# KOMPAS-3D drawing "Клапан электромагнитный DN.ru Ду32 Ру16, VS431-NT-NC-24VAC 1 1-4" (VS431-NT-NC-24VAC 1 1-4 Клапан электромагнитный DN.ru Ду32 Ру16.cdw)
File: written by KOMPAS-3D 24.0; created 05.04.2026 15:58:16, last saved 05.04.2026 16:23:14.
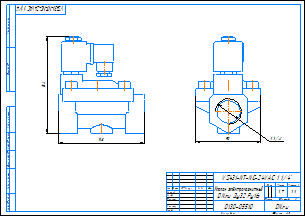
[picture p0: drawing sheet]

Document properties: c3d_UniqueCompID: ef56311e-7521-43dc-8291-0e6108b3d81d; Автор: artio; Класс точности: c; Знак неуказанной шероховатости: Шероховатость не задана; Рассекать на разрезах: Да; c3d_UniqueCompID: ef56311e-7521-43dc-8291-0e6108b3d81d; Автор: artio; Класс точности: c; Знак неуказанной шероховатости: Шероховатость не задана; Рассекать на разрезах: Да; c3d_UniqueCompID: ef56311e-7521-43dc-8291-0e6108b3d81d; Автор: artio; Класс точности: c; Знак неуказанной шероховатости: Шероховатость не задана; Рассекать на разрезах: Да; Автор: artio; Форматы листов документа: A3; Полное имя файла: VS431-NT-NC-24VAC 1 1-4 Клапан электромагнитный DN.ru Ду32 Ру16.m3d; Масса: 1.701; Наименование: Клапан электромагнитный DN.ru Ду32 Ру16; Количество листов документа: 1; Примечание: D130-05510

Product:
- Body: Тело 1  | qty 1
    Масса: 3.709873
- Part/product: Клапан электромагнитный DN.ru Ду32 Ру16  | designation VS431-NT-NC-24VAC 1 1-4
    Масса: 1.701
    Раздел спецификации: Прочие изделия
    Примечание: D130-05510
    additional columns: ef56311e-7521-43dc-8291-0e6108b3d81d; artio; c; Шероховатость не задана; Да

Views: Вид 1, Спереди
Referenced files in C:\Users\artio\OneDrive\Рабочий стол\Клапан электромагнитный DN.ru\VS431\VS431-ET-NC\: VS431-ET-NC-24VAC 3-4 Клапан электромагнитный DN.ru Ду20 Ру16.m3d, VS431-ET-NC-24VAC 3-4 Клапан электромагнитный DN.ru Ду20 Ру16.cdw
Referenced files in C:\Users\artio\OneDrive\Рабочий стол\Клапан электромагнитный DN.ru\VS431\VS431-NT-NC\: VS431-NT-NC-24VAC 1 1-4 Клапан электромагнитный DN.ru Ду32 Ру16.m3d
Referenced files in C:\Users\artio\OneDrive\Рабочий стол\Клапан электромагнитный DN.ru\VS431\VS431-NT-NC\VS431-NT-NC-24VAC\Ду32\: VS431-NT-NC-24VAC 1 1-4 Клапан электромагнитный DN.ru Ду32 Ру16.m3d
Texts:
  VS431-NT-NC-24VAC 1 1-4
  Клапан электромагнитный
  DN.ru Ду32 Ру16
  VS431-NT-NC-24VAC 1 1/4"
  VS431-NT-NC-24VAC 1 1/4"-
  Клапан электромагнитный DN.ru Ду32 Ру16
  VS431-NT-NC-24VAC 1 1-4 Клапан электромагнитный DN.ru Ду32 Ру16
Dimensions and other numbers on the sheet: 0; 3; 2; 4; 90; 1 1/4"; 1:1; 1; 1,7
